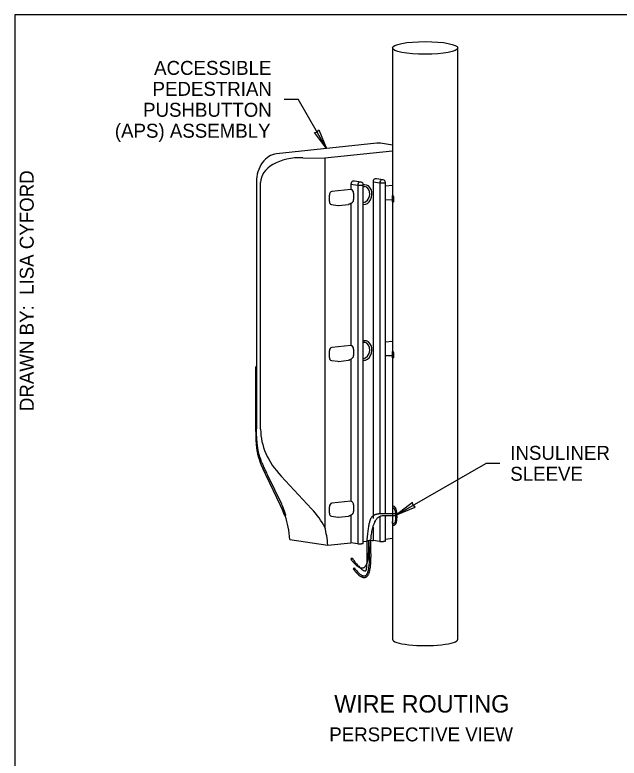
# Model space of a CAD drawing. Extents: x 99862 to 103151, y 100000 to 105076.
# Drawn here: x 99862 to 100554, y 101224 to 102076 of the extents above; entities that cross this region are included whole.
import ezdxf

# ---------------------------------------------------------------- set-up
doc = ezdxf.new("R2010")
doc.units = 0
for name, color, linetype in [('Level 1', 7, 'Continuous'), ('Level 15', 7, 'Continuous'), ('Level 18', 7, 'Continuous'), ('Level 20', 7, 'Continuous'), ('Level 31', 7, 'Continuous'), ('Level 33', 7, 'Continuous'), ('Level 42', 7, 'Continuous'), ('Level 62', 7, 'Continuous')]:
    doc.layers.add(name, color=color, linetype=linetype)

msp = doc.modelspace()

# ---------------------------------------------------------------- linework, layer by layer
at = {"layer": 'Level 1'}
msp.add_lwpolyline([(99862, 99999.5), (103151, 99999.5), (103151, 102075.5), (99862, 102075.5)], close=True, dxfattribs=at)
at = {"layer": 'Level 15'}
for p, q in [((100170.59, 101978.75), (100186.59, 101978.75)), ((100219.09, 101922.46), (100186.59, 101978.75)), ((100299.37, 101502.77), (100401.55, 101561.77)), ((100417.55, 101561.77), (100401.55, 101561.77))]:
    msp.add_line(p, q, dxfattribs=at)
for points in [[(100219.09, 101922.46), (100205.09, 101940.74), (100208.2, 101941.32), (100210.26, 101943.72)], [(100299.37, 101502.77), (100320.63, 101511.6), (100318.22, 101513.66), (100317.65, 101516.77)]]:
    msp.add_lwpolyline(points, close=True, dxfattribs=at)
at = {"layer": 'Level 18'}
for p, q in [((100281.3, 101504.43), (100297.27, 101504.13)), ((100283.18, 101501.98), (100297.4, 101501.98)), ((100248.37, 101453.03), (100246.94, 101451.94)), ((100250.77, 101442.11), (100249.44, 101441.09))]:
    msp.add_line(p, q, dxfattribs=at)
msp.add_ellipse((100267.67, 101473.08), major_axis=(-2.69, -0.35), ratio=0.103975, start_param=2.35204, end_param=6.98667, dxfattribs=at)
for points, degree in [([(100265.43, 101472.95), (100267.15, 101490.82), (100271.48, 101503.77), (100281.3, 101504.43)], 2), ([(100269.83, 101473.52), (100270.2, 101478.3), (100270.72, 101481.93), (100272.14, 101488.62), (100273.06, 101491.62), (100274.75, 101495.31), (100275.36, 101496.41), (100276.67, 101498.3), (100277.37, 101499.1), (100278.85, 101500.4), (100279.63, 101500.91), (100281.3, 101501.65), (100282.2, 101501.89), (100283.18, 101501.98)], 3), ([(100246.94, 101451.94), (100248.21, 101450.27), (100249.4, 101448.83), (100251.65, 101446.37), (100252.71, 101445.35), (100254.73, 101443.69), (100255.7, 101443.04), (100257.15, 101442.37), (100257.63, 101442.19), (100258.61, 101441.96), (100259.1, 101441.89), (100260.09, 101441.9), (100260.58, 101441.98), (100261.51, 101442.27), (100261.94, 101442.48), (100262.74, 101443.01), (100263.1, 101443.33), (100263.75, 101444.03), (100264.03, 101444.42), (100264.81, 101445.68), (100265.22, 101446.63), (100265.92, 101448.77), (100266.2, 101449.95), (100266.91, 101453.85), (100267.2, 101456.91), (100267.5, 101463.82), (100267.52, 101467.67), (100267.45, 101472.14), (100267.44, 101472.45), (100267.43, 101472.77)], 3), ([(100248.37, 101453.03), (100263.4, 101433.35), (100266.09, 101447.2), (100265.64, 101473)], 2), ([(100249.44, 101441.09), (100250.71, 101439.43), (100251.9, 101437.99), (100254.15, 101435.53), (100255.2, 101434.5), (100257.23, 101432.84), (100258.2, 101432.2), (100259.65, 101431.52), (100260.13, 101431.35), (100261.11, 101431.11), (100261.6, 101431.05), (100262.58, 101431.06), (100263.07, 101431.13), (100264, 101431.42), (100264.44, 101431.63), (100265.24, 101432.17), (100265.6, 101432.48), (100266.24, 101433.19), (100266.53, 101433.58), (100267.31, 101434.83), (100267.72, 101435.79), (100268.42, 101437.92), (100268.7, 101439.11), (100269.41, 101443.01), (100269.69, 101446.07), (100270, 101452.98), (100270.02, 101456.83), (100269.89, 101464.76), (100269.75, 101468.79), (100269.57, 101473.52)], 3), ([(100250.77, 101442.11), (100252.02, 101440.48), (100253.18, 101439.08), (100255.35, 101436.7), (100256.35, 101435.74), (100258.22, 101434.2), (100259.07, 101433.64), (100260.27, 101433.09), (100260.65, 101432.95), (100261.38, 101432.77), (100261.74, 101432.73), (100262.41, 101432.73), (100262.74, 101432.78), (100263.34, 101432.97), (100263.64, 101433.11), (100264.18, 101433.48), (100264.44, 101433.7), (100264.92, 101434.23), (100265.15, 101434.54), (100265.79, 101435.57), (100266.15, 101436.4), (100266.79, 101438.35), (100267.06, 101439.46), (100268.19, 101445.68), (100268.4, 101452.69), (100268.21, 101464.41), (100268.09, 101468.09), (100267.36, 101473.32)], 3)]:
    msp.add_open_spline(points, degree=degree, dxfattribs=at)
at = {"layer": 'Level 31'}
for p, q in [((100294.51, 102037.64), (100294.51, 101468.51)), ((100369.51, 101360.3), (100369.51, 102037.64)), ((100294.51, 101511.33), (100294.84, 101511.27)), ((100294.51, 101468.51), (100294.51, 101360.3))]:
    msp.add_line(p, q, dxfattribs=at)
msp.add_ellipse((100332.01, 102037.64), major_axis=(-37.5, 0), ratio=0.194841, dxfattribs=at)
for centre, major_axis, ratio, start_param, end_param in [((100294.96, 101501.91), (0.18, -9.37), 0.151332, 2.932249, 3.096468), ((100294.96, 101501.91), (0.18, -9.37), 0.151332, 6.073842, 6.23806), ((100332.01, 101360.3), (-37.5, 0), 0.194841, 6.283185, 9.424778)]:
    msp.add_ellipse(centre, major_axis=major_axis, ratio=ratio, start_param=start_param, end_param=end_param, dxfattribs=at)
for points, degree in [([(100294.95, 101860.87), (100294.43, 101861.16), (100294.44, 101868.72), (100294.88, 101868.43)], 2), ([(100294.88, 101868.43), (100295.7, 101868.74), (100296.12, 101861.03), (100295.09, 101860.86)], 2), ([(100294.95, 101682.29), (100294.43, 101682.58), (100294.44, 101690.14), (100294.88, 101689.85)], 2), ([(100294.88, 101689.85), (100295.7, 101690.16), (100296.12, 101682.45), (100295.09, 101682.28)], 2), ([(100294.51, 101513.58), (100296.32, 101512.68), (100296.51, 101512.54), (100296.87, 101512.22), (100297.04, 101512.04), (100297.48, 101511.47), (100297.7, 101511.07), (100298.08, 101510.24), (100298.24, 101509.8), (100298.52, 101508.87), (100298.65, 101508.38), (100298.97, 101506.84), (100299.13, 101505.72), (100299.35, 101503.4), (100299.41, 101502.19), (100299.43, 101499.82), (100299.39, 101498.64), (100299.2, 101496.44), (100299.05, 101495.41), (100298.72, 101494.01), (100298.59, 101493.58), (100298.28, 101492.74), (100298.09, 101492.34), (100297.69, 101491.75), (100297.54, 101491.56), (100297.16, 101491.19), (100296.93, 101491.01), (100296.39, 101490.71), (100296.07, 101490.6), (100295.39, 101490.5), (100295.05, 101490.51), (100294.73, 101490.58)], 3), ([(100295.08, 101511.08), (100298.08, 101509.57), (100298.29, 101491.86), (100295.15, 101492.54)], 2), ([(100294.84, 101492.74), (100294.63, 101493.2), (100294.48, 101493.92), (100294.51, 101495.31)], 2)]:
    msp.add_open_spline(points, degree=degree, dxfattribs=at)
at = {"layer": 'Level 33'}
for p, q in [((100276.49, 101928.52), (100161.69, 101916.41)), ((100294.51, 101926.4), (100280.91, 101928.42)), ((100294.51, 101919.35), (100217.08, 101911.19)), ((100191.92, 101911.9), (100217.08, 101911.19)), ((100217.08, 101911.19), (100217.08, 101488.71)), ((100138.73, 101884.22), (100138.73, 101670.91)), ((100143.56, 101600.75), (100143.56, 101883.5)), ((100247.04, 101881.61), (100247.04, 101875.45)), ((100250.48, 101884.95), (100249.33, 101884.82)), ((100258.65, 101883.79), (100250.92, 101884.94)), ((100261.2, 101472.39), (100261.2, 101880.82)), ((100272.29, 101884.27), (100272.29, 101603.26)), ((100275.74, 101887.61), (100274.59, 101887.49)), ((100283.9, 101886.45), (100276.18, 101887.6)), ((100286.46, 101504.33), (100286.46, 101883.48)), ((100246.84, 101875.43), (100225.23, 101873.15)), ((100286.46, 101879.61), (100294.51, 101880.46)), ((100222.36, 101861.68), (100222.36, 101869.12)), ((100250.09, 101871.27), (100250.09, 101863.83)), ((100286.46, 101863.81), (100294.51, 101863.79)), ((100224.67, 101858.28), (100231.91, 101857.2)), ((100232.86, 101857.18), (100244.05, 101858.36)), ((100246.75, 101859.39), (100248.92, 101861.13)), ((100247.04, 101859.62), (100247.04, 101696.87)), ((100246.84, 101696.85), (100225.23, 101694.57)), ((100286.46, 101701.03), (100294.51, 101701.88)), ((100222.36, 101683.11), (100222.36, 101690.55)), ((100250.09, 101692.69), (100250.09, 101685.25)), ((100286.46, 101685.23), (100294.51, 101685.22)), ((100224.67, 101679.7), (100231.91, 101678.62)), ((100232.86, 101678.6), (100244.05, 101679.78)), ((100246.75, 101680.81), (100248.92, 101682.55)), ((100247.04, 101681.04), (100247.04, 101518.29)), ((100137.85, 101671.21), (100137.85, 101601.77)), ((100138.73, 101670.91), (100138.73, 101601.47)), ((100272.29, 101603.26), (100272.29, 101498.71)), ((100151.84, 101547.98), (100151.09, 101549.53)), ((100149.36, 101548.4), (100165.93, 101513.75)), ((100167.67, 101514.88), (100151.84, 101547.98)), ((100201.93, 101509.77), (100167.04, 101547.16)), ((100168.38, 101513.32), (100167.67, 101514.88)), ((100246.84, 101518.27), (100225.23, 101515.99)), ((100222.36, 101504.53), (100222.36, 101511.97)), ((100250.09, 101514.12), (100250.09, 101506.68)), ((100224.67, 101501.12), (100231.91, 101500.04)), ((100232.86, 101500.02), (100244.05, 101501.2)), ((100246.75, 101502.23), (100248.92, 101503.97)), ((100247.04, 101502.46), (100247.04, 101470.9)), ((100286.46, 101475.05), (100286.46, 101501.98)), ((100272.29, 101488.79), (100272.29, 101473.56)), ((100177.11, 101474.58), (100220.56, 101468.1)), ((100261.2, 101472.39), (100264.98, 101472.79)), ((100261.2, 101470.11), (100261.2, 101472.39)), ((100270.31, 101473.35), (100272.29, 101473.56)), ((100280.02, 101472.41), (100272.29, 101473.56)), ((100285.39, 101472.48), (100284.24, 101472.36)), ((100286.46, 101475.06), (100294.51, 101475.91)), ((100286.46, 101472.77), (100286.46, 101475.05)), ((100220.56, 101468.1), (100247.04, 101470.9)), ((100254.76, 101469.75), (100247.04, 101470.9)), ((100260.14, 101469.82), (100258.99, 101469.7))]:
    msp.add_line(p, q, dxfattribs=at)
for points in [[(100261.21, 101878.98), (100261.4, 101879.01), (100261.52, 101879.03)], [(100261.21, 101700.4), (100261.4, 101700.43), (100261.52, 101700.45)]]:
    msp.add_lwpolyline(points, dxfattribs=at)
for centre, radius, start, end in [((100258.2, 101880.82), 3, 0, 81.51737), ((100283.46, 101883.48), 3, 0, 81.51737), ((100232.47, 101860.91), 3.75, 261.51737, 276.02174), ((100232.47, 101682.33), 3.75, 261.51737, 276.02174), ((100141.6, 101671.21), 3.75, 139.93574, 180), ((100173.15, 101504.73), 3.24, 202.95642, 243.4546), ((100232.47, 101503.75), 3.75, 261.51737, 276.02174)]:
    msp.add_arc(centre, radius, start, end, dxfattribs=at)
for centre, major_axis, ratio, start_param, end_param in [((100276.49, 101898.75), (4.43, 29.67), 0.759279, 0, 0.193955), ((100161.69, 101886.64), (4.43, 29.67), 0.759279, 0.193955, 1.764752), ((100191.92, 101882.13), (48.35, -2.2), 0.614587, 1.598727, 3.169524), ((100249.33, 101881.85), (0.44, 2.97), 0.759279, 0.193955, 1.764752), ((100250.48, 101881.97), (0.44, 2.97), 0.759279, 0, 0.193955), ((100262.53, 101869.55), (-1.66, -11.13), 0.759279, 0.038851, 3.335548), ((100262.53, 101869.55), (-1.66, -11.13), 0.759279, 3.335548, 3.490652), ((100274.59, 101884.51), (0.44, 2.97), 0.759279, 0.193955, 1.764752), ((100275.74, 101884.63), (0.44, 2.97), 0.759279, 0, 0.193955), ((100225.23, 101869.43), (-0.55, -3.71), 0.759279, 3.335548, 4.906344), ((100246.84, 101871.71), (4.2, 1.47), 0.820766, 1.246381, 1.291135), ((100246.89, 101871.75), (1.26, -3.61), 0.815203, 1.165356, 2.691399), ((100261.33, 101869.73), (1.38, 9.27), 0.759279, 3.31837, 6.29201), ((100246.89, 101864.31), (-1.26, 3.61), 0.815203, 3.421254, 4.306949), ((100225.23, 101861.99), (-0.55, -3.71), 0.759279, 4.906344, 6.283185), ((100262.53, 101690.97), (-1.66, -11.13), 0.759279, 0.038851, 3.335548), ((100262.53, 101690.97), (-1.66, -11.13), 0.759279, 3.335548, 3.490652), ((100225.23, 101690.85), (-0.55, -3.71), 0.759279, 3.335548, 4.906344), ((100246.84, 101693.13), (4.2, 1.47), 0.820766, 1.246381, 1.291135), ((100246.89, 101693.17), (1.26, -3.61), 0.815203, 1.165356, 2.691399), ((100261.33, 101691.15), (1.38, 9.27), 0.759279, 3.31837, 6.29201), ((100246.89, 101685.73), (-1.26, 3.61), 0.815203, 3.421254, 4.306949), ((100225.23, 101683.41), (-0.55, -3.71), 0.759279, 4.906344, 6.283185), ((100312.84, 101595.97), (-169.21, 7.69), 0.614587, 0.027931, 0.56094), ((100225.23, 101512.27), (-0.55, -3.71), 0.759279, 3.335548, 4.906344), ((100246.84, 101514.55), (4.2, 1.47), 0.820766, 1.246381, 1.291135), ((100246.89, 101514.59), (1.26, -3.61), 0.815203, 1.165356, 2.691399), ((100056.14, 101460.96), (-169.21, 7.69), 0.614587, 3.484746, 3.702533), ((100246.89, 101507.15), (-1.26, 3.61), 0.815203, 3.421254, 4.306949), ((100097.23, 101454.83), (-15.49, -103.85), 0.759279, 1.873697, 2.149994), ((100225.23, 101504.83), (-0.55, -3.71), 0.759279, 4.906344, 6.283185), ((100140.68, 101448.35), (-15.49, -103.85), 0.759279, 1.873697, 2.079974), ((100282.31, 101472.65), (-3, 0), 0.12543, 0.699253, 2.27005), ((100283.46, 101472.77), (-3, 0), 0.12543, 2.27005, 3.141593), ((100257.06, 101469.99), (-3, 0), 0.12543, 0.699253, 2.27005), ((100258.2, 101470.11), (-3, 0), 0.12543, 2.27005, 3.141593)]:
    msp.add_ellipse(centre, major_axis=major_axis, ratio=ratio, start_param=start_param, end_param=end_param, dxfattribs=at)
for points in [[(100261.52, 101879.03), (100261.91, 101879.07), (100262.29, 101879.06), (100262.66, 101879.01)], [(100246.75, 101859.39), (100245.82, 101858.65), (100244.92, 101858.51), (100244.05, 101858.37)], [(100261.52, 101700.45), (100261.91, 101700.5), (100262.29, 101700.48), (100262.66, 101700.43)], [(100246.75, 101680.81), (100245.82, 101680.07), (100244.92, 101679.93), (100244.05, 101679.79)], [(100137.85, 101601.77), (100137.83, 101582.73), (100141.83, 101564.1), (100149.36, 101548.4)], [(100151.09, 101549.53), (100143.44, 101564.74), (100139.13, 101582.9), (100138.73, 101601.47)], [(100165.93, 101513.75), (100167.51, 101510.47), (100168.92, 101507.02), (100170.16, 101503.47)], [(100172.3, 101502.7), (100171.08, 101506.5), (100169.86, 101510.01), (100168.38, 101513.32)], [(100171.7, 101501.83), (100172.17, 101501.79), (100172.37, 101502.08), (100172.3, 101502.7)], [(100246.75, 101502.23), (100245.82, 101501.49), (100244.92, 101501.35), (100244.05, 101501.21)]]:
    msp.add_open_spline(points, degree=2, dxfattribs=at)
at = {"layer": 'Level 42'}
for p, q in [((100247.04, 101881.61), (100254.76, 101880.45)), ((100258.2, 101883.79), (100257.06, 101883.67)), ((100272.29, 101884.27), (100280.02, 101883.12)), ((100280.02, 101883.12), (100280.02, 101504.27)), ((100283.46, 101886.46), (100282.31, 101886.34)), ((100284.24, 101883.07), (100285.39, 101883.19)), ((100254.76, 101880.45), (100254.76, 101469.75)), ((100258.99, 101880.41), (100260.14, 101880.53)), ((100280.02, 101501.07), (100280.02, 101472.41))]:
    msp.add_line(p, q, dxfattribs=at)
for centre, major_axis, ratio, start_param, end_param in [((100257.06, 101880.7), (0.44, 2.97), 0.759279, 0.193955, 1.764752), ((100258.2, 101880.82), (-0.44, -2.97), 0.759279, 3.141593, 3.335548), ((100258.2, 101880.82), (-3, 0), 0.12543, 2.27005, 3.141593), ((100282.31, 101883.36), (0.44, 2.97), 0.759279, 0.193955, 1.764752), ((100282.31, 101883.36), (-3, 0), 0.12543, 0.699253, 2.27005), ((100283.46, 101883.48), (-0.44, -2.97), 0.759279, 3.141593, 3.335548), ((100283.46, 101883.48), (-3, 0), 0.12543, 2.27005, 3.141593), ((100257.06, 101880.7), (-3, 0), 0.12543, 0.699253, 2.27005)]:
    msp.add_ellipse(centre, major_axis=major_axis, ratio=ratio, start_param=start_param, end_param=end_param, dxfattribs=at)

# ---------------------------------------------------------------- texts
at = {"layer": 'Level 20'}
for s, height, p in [('ACCESSIBLE', 16, (100021.52, 102006.75)), ('PEDESTRIAN', 16, (100019.72, 101982.75)), ('PUSHBUTTON', 16, (100008.87, 101958.75)), ('(APS) ASSEMBLY', 16, (99976.55, 101934.75)), ('WIRE ROUTING', 20, (100227.83, 101276.29)), ('PERSPECTIVE VIEW', 16, (100222.19, 101243.29))]:
    msp.add_text(s, height=height, dxfattribs=at).set_placement(p)
for s, p in [('INSULINER', (100429.55, 101565.77)), ('SLEEVE', (100429.55, 101541.77))]:
    msp.add_text(s, height=16, rotation=360, dxfattribs=at).set_placement(p)
at = {"layer": 'Level 62'}
msp.add_text('DRAWN BY:  LISA CYFORD', height=16, rotation=90, dxfattribs=at).set_placement((99883.57, 101621.59))

doc.saveas('drawing.dxf')
